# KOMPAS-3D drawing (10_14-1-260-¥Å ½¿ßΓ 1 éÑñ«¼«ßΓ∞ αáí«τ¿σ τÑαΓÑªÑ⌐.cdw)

Views: Вид 1
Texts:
  Smirnov NIkita
  Схема Э3
  Текст на чертеже
  Размерные надписи
  Шероховатость
  Линия-выноска #1
  Линия-выноска #2
  Линия-выноска #3
  Отклонения формы и база
  Заголовок таблицы
  Ячейка таблицы
  Стрелка вида
  Обозначение изменения
  Фигурная скобка
  Номер узла
  Марка координационной оси
  VRCB
  Выносная надпись
  Обозначение узла
  Марка/позиционное обозначение с линией-выноской
  Марка/позиционное обозначение на линии
  Марка/позиционное обозначение без линии-выноски
  Лит-Масса-Масштаб
  Материал-Предприятие
  Normal
  Title Specification
  Body Specification ( left align )
  Body Specificaton ( centered )
  Обычный
  Термин
  Список определений
  Адрес
  Цитаты
  Форматированный
  Courier New
  Z-конец формы
  Z-начало формы
  Additional DXF text style 0
  heading 1
  Знак Знак Знак Знак Знак Знак
  Verdana
  Абзац Знак
  Body Text
  Body Text 3
  Title
  Без имени
  ТекстШаг1
  Txt
  Шрифт 2.5
  Заголовки
  Simplex
  txt
  MS Sans Serif
  TXT
  style2
  Definition Term
  Definition List
  Address
  Blockquote
  Preformatted
  z-Bottom of Form
  z-Top of Form
  Table Contents
  Table Heading
  ООббыыччнныыйй
  Денис
  header
  heading 2
  AGOpus
  footer
  HeliosLight
  Pa3
  Pa1
  heading 8
  heading 3
  heading 6
  heading 7
  russ
  ТТееррммиинн
  ССппииссоокк ооппррееддееллеенниийй
  ААддрреесс
  ЦЦииттааттыы
  ФФооррммааттиирроовваанннныыйй
  Z-ккооннеецц ффооррммыы
  Z-ннааччааллоо ффооррммыы
  heading 4
  heading 5
  heading 9
  ГОСТ_МНЕ
  ESK - Обозначение
  Подпись в квадратике
  цепи
  GOST 2.304 type A
  rustxt
  ссылки
  текст переноса
  табл
  Тексты. 3,2
  ЗОНА_привяз
  Маркировка
  клеммы, контакты
  тексты табл
  RUSTXT
  NormalParagraphStyle
  Три с половиной
  маркировка
  ISOCP
  Tahoma
  FR5
  Лист
  Ведомость рабочих чертежей комплекта 260-ЭП
  Опросный лист на КТП-Б(М)
  Блок опорных изоляторов 6 кВ
  Ведомость ссылочных и прилагаемых документов
  Прилагаемые документы
  Расположение оборудования на ПС. План.
  Расположение оборудования на ПС. Виды
  Схема расположения строительных конструкций
  Опросный лист на заземлитель нейтрали
  ЗОН СЭЩ-110/II УХЛ1
  Опросный лист на шкаф зажимов трансформатора
  напряжения 110 кВ
  CONTINUOUS0
  Принципиальная схема управления, автоматики
  и сигнализации ВЛ - 110 кВ W5G(W6G)
  АББЧ.656.453.009 Э3-РЗА
  Схема организации сигнально-
  оперативных  шинок в помещении ОПУ
  Ведомость рабочих чертежей
  комплекта 260-ЭП
  Реконструкция ПС 110 кВ Опорная
  (замена трансформаторов 16МВА на 40МВА)
  ГИП
  Маленкин
  Н.контр.
  Разраб.
  Скахин
Dimensions and other numbers on the sheet: 10/14-1-260-ЭП; 7; 1,8; 2,5; 2.5; 3,2_; 3,2 (надписи); 2,5 (контакты, клеммы); 2,3_; 2,5_01; 3.5; 2.5 курсив; 3,5; 3,2; 2,5_3; 3,5_01; 3,5_tabl; 5_заголовок; 3,2_зона не привяз; 2,5 грязносинь; 5; 3,2 элементы; 3,2 линия; 3,2 таблица; 3.2 маркировка; 2.5_Э5_надписи; 2.5_Э5_ссылки; 2.5_кабель; 3.2; 2.5 надписи; 3,2 (Зоны); 5,0_белый_подчёркнутый; 3 и 5; 3.2 фиол; 1; 2; 3; 10/14-1-113-ЭП лист 2; 10/14-1-113-ЭП лист 3; 10/14-1-113-КС лист 3; 10/14-1-113-ЭП.ОЛ3; 10/14-1-051-ЭП.ОЛ3; 1:1; 86/02-19-01-113-ЭП-; 11.12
